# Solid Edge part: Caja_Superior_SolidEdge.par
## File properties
Author: jonat
Template: ISO Metric Part.par
Last saved by: Will Familia
Revision: 6
Application: Solid Edge
Username: jonat
Densidad: 1385.000 kg/m^3
Precisión: 0.990
Material: PVC
Estilo de cara: Tan
Estilo de relleno: ANSI34(Plastic)
Estilo virtual: ANSI34(Plastic)
Grupos: Non-metals\Plastics
NombreDeBiblioteca: Materials
Coef. of Thermal Exp: 9e-05
Thermal Conductivity: 1.5
Specific Heat: 0.0
Modulus of Elasticity: 2757903000.0
Poisson's Ratio: 0.4
Yield Stress: 6894757.0
Ultimate Stress: 0.0
Elongation: 0.0
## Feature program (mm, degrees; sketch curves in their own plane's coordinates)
sketch for "unnamed Protrusion 1" plane through (0, 0, 0) normal (0, 0, 1) x-axis (1, 0, 0)
  line (53.5, -43.85) -> (53.5, 43.85)
  line (53.5, 43.85) -> (-53.5, 43.85)
  line (-53.5, 43.85) -> (-53.5, -43.85)
  line (-53.5, -43.85) -> (53.5, -43.85)
extrude "unnamed Protrusion 1" add finite 49.84 along +normal
sketch for "Corte_1" #1 plane through (53.5, 0, 24.92) normal (1, 0, 0) x-axis (0, 1, 0)
  line (-30, 10.62) -> (-23, 10.62)
  line (-23, 10.62) -> (-23, 24.92)
  line (-23, 24.92) -> (-43.85, 24.92)
  line (-43.85, 24.92) -> (-43.85, -8.38)
  line (-43.85, -8.38) -> (-30, -8.38)
  line (-30, -8.38) -> (-30, 10.62)
sketch for "Corte_1" #2 plane through (53.5, 0, 24.92) normal (1, 0, 0) x-axis (0, 1, 0)
  line (43.85, -8.38) -> (30, -8.38)
  line (30, -8.38) -> (30, 10.62)
  line (30, 10.62) -> (23, 10.62)
  line (23, 10.62) -> (23, 24.92)
  line (23, 24.92) -> (43.85, 24.92)
  line (43.85, 24.92) -> (43.85, -8.38)
extrude "Corte_1" cut finite 127.4104 along -normal
sketch for "Corte_2" plane through (0, -43.85, 8.27) normal (0, -1, 0) x-axis (1, 0, 0)
  line (-45.925, -19.87) -> (45.925, -19.87)
  line (45.925, -19.87) -> (45.925, 3.33)
  line (45.925, 3.33) -> (-45.925, 3.33)
  line (-45.925, 3.33) -> (-45.925, -19.87)
extrude "Corte_2" cut finite 194.2447 along -normal
sketch for "Corte_3" plane through (53.5, 0, 24.92) normal (1, 0, 0) x-axis (0, 1, 0)
  line (-2.7, -13.38) -> (-2.7, -14.88)
  line (-2.7, -14.88) -> (2.3, -14.88)
  line (2.3, -14.88) -> (2.3, -13.38)
  line (2.3, -13.38) -> (-2.7, -13.38)
extrude "Corte_3" cut finite 132.7841 along -normal
sketch for "Corte_4" plane through (0, -23, 42.69) normal (0, -1, 0) x-axis (1, 0, 0)
  line (-51.5, 9.15) -> (51.5, 9.15)
  line (51.5, 9.15) -> (51.5, 5.15)
  line (51.5, 5.15) -> (-51.5, 5.15)
  line (-51.5, 5.15) -> (-51.5, 9.15)
extrude "Corte_4" cut finite 87.3039 along -normal
sketch for "Corte_5" plane through (0, 0, 47.84) normal (0, 0, 1) x-axis (1, 0, 0)
  line (51.5, -21) -> (51.5, 21)
  line (51.5, 21) -> (-51.5, 21)
  line (-51.5, 21) -> (-51.5, -21)
  line (-51.5, -21) -> (51.5, -21)
extrude "Corte_5" cut finite 5.3 along -normal
sketch for "Corte_6" #1 plane through (53.5, 0, 24.92) normal (1, 0, 0) x-axis (0, 1, 0)
  line (-23, 22.92) -> (-23, 24.92)
  line (-23, 24.92) -> (23, 24.92)
  arc centre (0, -108.33) radius 133.25 from (-23, 22.92) to (23, 22.92) cw
sketch for "Corte_6" #2 plane through (53.5, 0, 24.92) normal (1, 0, 0) x-axis (0, 1, 0)
  line (-23, 24.92) -> (23, 24.92)
  line (23, 24.92) -> (23, 22.92)
  arc centre (0, -108.33) radius 133.25 from (-23, 22.92) to (23, 22.92) cw
extrude "Corte_6" cut finite 110.3293 along -normal
fillet "Redondeo_1" radius 1.4
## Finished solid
Body 1: solid body, 66 faces, 155 edges, 91 vertices.
  Faces by surface: plane 32, cylinder 25, sphere 7, torus 2
  Edges by curve: line 111, circle 32, ellipse 8, intersection 4
Bounding box of the edges (mm; curved faces can reach further): 107.000 x 87.700 x 49.840, from (-53.5, -43.85, 0) to (53.5, 43.85, 49.84).
Cylindrical faces by radius (mm): R1.4 x23, R133.25 x2
Toroidal faces (ring radius, tube radius in mm): R131.85 r1.4 x2
Spherical faces by radius (mm): R1.4 x7
Planar faces by outward normal: +x 3, +y 6, +z 9, -x 3, -y 6, -z 5
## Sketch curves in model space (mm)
line (0, 0, 35.54) -> (0, -47.699, 35.54)
line (-46.5, 30, 35.54) -> (-46.5, 28, 35.54)
line (-46.5, 28, 35.54) -> (-48.5, 28, 35.54)
line (-48.5, 28, 35.54) -> (-48.5, 30, 35.54)
line (-48.5, 30, 35.54) -> (-46.5, 30, 35.54)
line (46.5, 30, 35.54) -> (46.5, 28, 35.54)
line (46.5, 28, 35.54) -> (48.5, 28, 35.54)
line (48.5, 28, 35.54) -> (48.5, 30, 35.54)
line (48.5, 30, 35.54) -> (46.5, 30, 35.54)
line (2, 30, 35.54) -> (2, 28, 35.54)
line (2, 28, 35.54) -> (4, 28, 35.54)
line (4, 28, 35.54) -> (4, 30, 35.54)
line (4, 30, 35.54) -> (2, 30, 35.54)
line (7, 30, 35.54) -> (7, 28, 35.54)
line (7, 28, 35.54) -> (9, 28, 35.54)
line (9, 28, 35.54) -> (9, 30, 35.54)
line (9, 30, 35.54) -> (7, 30, 35.54)
line (12, 30, 35.54) -> (12, 28, 35.54)
line (12, 28, 35.54) -> (14, 28, 35.54)
line (14, 28, 35.54) -> (14, 30, 35.54)
line (14, 30, 35.54) -> (12, 30, 35.54)
line (18, 30, 35.54) -> (18, 28, 35.54)
line (18, 28, 35.54) -> (20, 28, 35.54)
line (20, 28, 35.54) -> (20, 30, 35.54)
line (20, 30, 35.54) -> (18, 30, 35.54)
line (24, 30, 35.54) -> (24, 28, 35.54)
line (24, 28, 35.54) -> (26, 28, 35.54)
line (26, 28, 35.54) -> (26, 30, 35.54)
line (26, 30, 35.54) -> (24, 30, 35.54)
line (29.5, 30, 35.54) -> (29.5, 28, 35.54)
line (29.5, 28, 35.54) -> (31.5, 28, 35.54)
line (31.5, 28, 35.54) -> (31.5, 30, 35.54)
line (31.5, 30, 35.54) -> (29.5, 30, 35.54)
line (35, 30, 35.54) -> (35, 28, 35.54)
line (35, 28, 35.54) -> (37, 28, 35.54)
line (37, 28, 35.54) -> (37, 30, 35.54)
line (37, 30, 35.54) -> (35, 30, 35.54)
line (40.5, 30, 35.54) -> (40.5, 28, 35.54)
line (40.5, 28, 35.54) -> (42.5, 28, 35.54)
line (42.5, 28, 35.54) -> (42.5, 30, 35.54)
line (42.5, 30, 35.54) -> (40.5, 30, 35.54)
line (-2, 30, 35.54) -> (-2, 28, 35.54)
line (-2, 28, 35.54) -> (-4, 28, 35.54)
line (-4, 28, 35.54) -> (-4, 30, 35.54)
line (-4, 30, 35.54) -> (-2, 30, 35.54)
line (-7, 30, 35.54) -> (-7, 28, 35.54)
line (-7, 28, 35.54) -> (-9, 28, 35.54)
line (-9, 28, 35.54) -> (-9, 30, 35.54)
line (-9, 30, 35.54) -> (-7, 30, 35.54)
line (-12, 30, 35.54) -> (-12, 28, 35.54)
line (-12, 28, 35.54) -> (-14, 28, 35.54)
line (-14, 28, 35.54) -> (-14, 30, 35.54)
line (-14, 30, 35.54) -> (-12, 30, 35.54)
line (-18, 30, 35.54) -> (-18, 28, 35.54)
line (-18, 28, 35.54) -> (-20, 28, 35.54)
line (-20, 28, 35.54) -> (-20, 30, 35.54)
line (-20, 30, 35.54) -> (-18, 30, 35.54)
line (-24, 30, 35.54) -> (-24, 28, 35.54)
line (-24, 28, 35.54) -> (-26, 28, 35.54)
line (-26, 28, 35.54) -> (-26, 30, 35.54)
line (-26, 30, 35.54) -> (-24, 30, 35.54)
line (-29.5, 30, 35.54) -> (-29.5, 28, 35.54)
line (-29.5, 28, 35.54) -> (-31.5, 28, 35.54)
line (-31.5, 28, 35.54) -> (-31.5, 30, 35.54)
line (-31.5, 30, 35.54) -> (-29.5, 30, 35.54)
line (-35, 30, 35.54) -> (-35, 28, 35.54)
line (-35, 28, 35.54) -> (-37, 28, 35.54)
line (-37, 28, 35.54) -> (-37, 30, 35.54)
line (-37, 30, 35.54) -> (-35, 30, 35.54)
line (-40.5, 30, 35.54) -> (-40.5, 28, 35.54)
line (-40.5, 28, 35.54) -> (-42.5, 28, 35.54)
line (-42.5, 28, 35.54) -> (-42.5, 30, 35.54)
line (-42.5, 30, 35.54) -> (-40.5, 30, 35.54)
line (46.5, -30, 35.54) -> (46.5, -28, 35.54)
line (46.5, -28, 35.54) -> (48.5, -28, 35.54)
line (48.5, -28, 35.54) -> (48.5, -30, 35.54)
line (48.5, -30, 35.54) -> (46.5, -30, 35.54)
line (2, -30, 35.54) -> (2, -28, 35.54)
line (2, -28, 35.54) -> (4, -28, 35.54)
line (4, -28, 35.54) -> (4, -30, 35.54)
line (4, -30, 35.54) -> (2, -30, 35.54)
line (7, -30, 35.54) -> (7, -28, 35.54)
line (7, -28, 35.54) -> (9, -28, 35.54)
line (9, -28, 35.54) -> (9, -30, 35.54)
line (9, -30, 35.54) -> (7, -30, 35.54)
line (12, -30, 35.54) -> (12, -28, 35.54)
line (12, -28, 35.54) -> (14, -28, 35.54)
line (14, -28, 35.54) -> (14, -30, 35.54)
line (14, -30, 35.54) -> (12, -30, 35.54)
line (18, -30, 35.54) -> (18, -28, 35.54)
line (18, -28, 35.54) -> (20, -28, 35.54)
line (20, -28, 35.54) -> (20, -30, 35.54)
line (20, -30, 35.54) -> (18, -30, 35.54)
line (24, -30, 35.54) -> (24, -28, 35.54)
line (24, -28, 35.54) -> (26, -28, 35.54)
line (26, -28, 35.54) -> (26, -30, 35.54)
line (26, -30, 35.54) -> (24, -30, 35.54)
line (29.5, -30, 35.54) -> (29.5, -28, 35.54)
line (29.5, -28, 35.54) -> (31.5, -28, 35.54)
line (31.5, -28, 35.54) -> (31.5, -30, 35.54)
line (31.5, -30, 35.54) -> (29.5, -30, 35.54)
line (35, -30, 35.54) -> (35, -28, 35.54)
line (35, -28, 35.54) -> (37, -28, 35.54)
line (37, -28, 35.54) -> (37, -30, 35.54)
line (37, -30, 35.54) -> (35, -30, 35.54)
line (40.5, -30, 35.54) -> (40.5, -28, 35.54)
line (40.5, -28, 35.54) -> (42.5, -28, 35.54)
line (42.5, -28, 35.54) -> (42.5, -30, 35.54)
line (42.5, -30, 35.54) -> (40.5, -30, 35.54)
line (-2, -30, 35.54) -> (-2, -28, 35.54)
line (-2, -28, 35.54) -> (-4, -28, 35.54)
line (-4, -28, 35.54) -> (-4, -30, 35.54)
line (-4, -30, 35.54) -> (-2, -30, 35.54)
line (-7, -30, 35.54) -> (-7, -28, 35.54)
line (-7, -28, 35.54) -> (-9, -28, 35.54)
line (-9, -28, 35.54) -> (-9, -30, 35.54)
line (-9, -30, 35.54) -> (-7, -30, 35.54)
line (-12, -30, 35.54) -> (-12, -28, 35.54)
line (-12, -28, 35.54) -> (-14, -28, 35.54)
line (-14, -28, 35.54) -> (-14, -30, 35.54)
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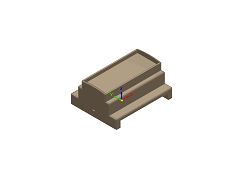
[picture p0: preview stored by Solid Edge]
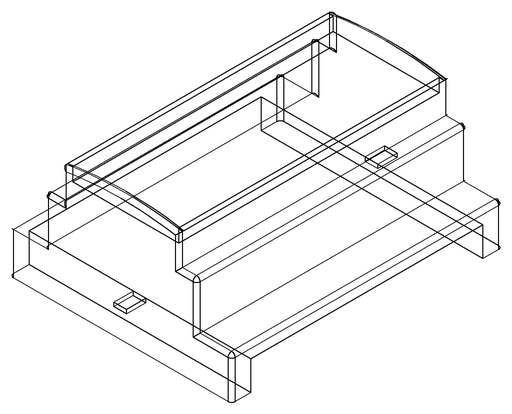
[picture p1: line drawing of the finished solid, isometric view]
